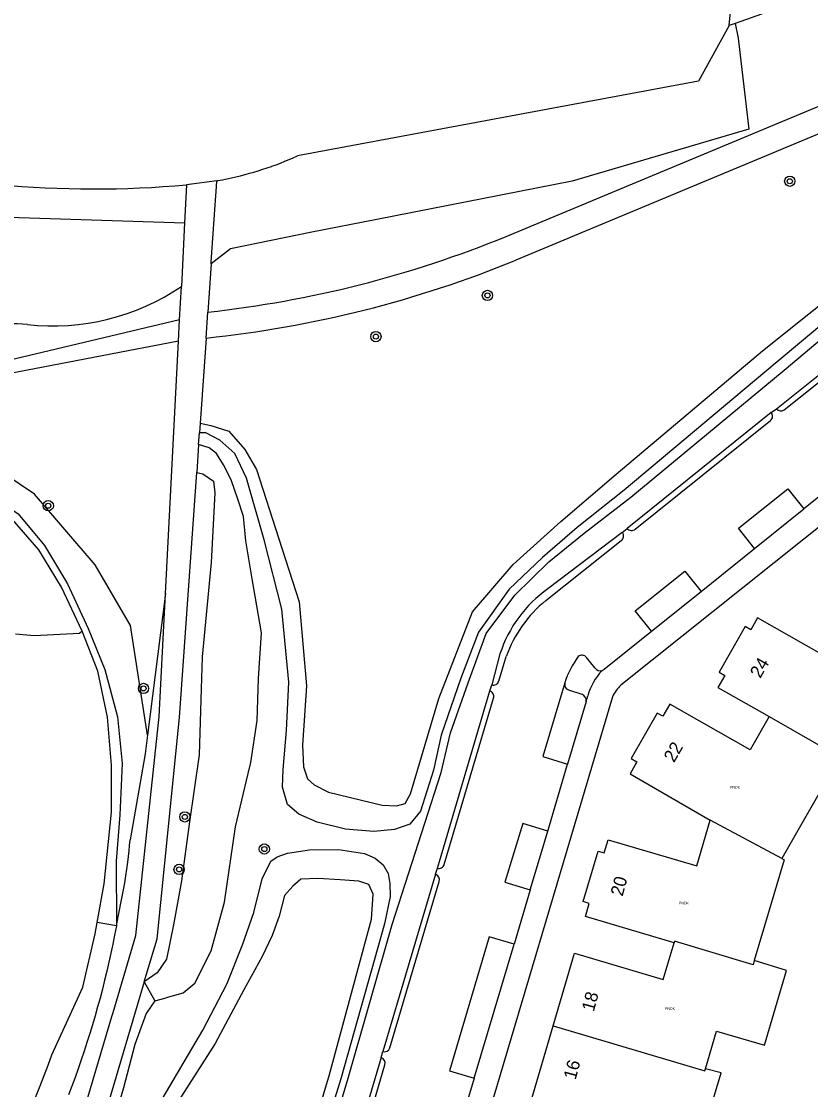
# Model space of a CAD drawing. Extents: x 131000 to 133013, y 393000 to 396501.
# Drawn here: x 131784.2 to 131845.9, y 393574.7 to 393658.1 of the extents above; entities that cross this region are included whole.
import ezdxf

# ---------------------------------------------------------------- set-up
doc = ezdxf.new("R2010")
doc.units = 0
for name, color, linetype in [('gg-anno-huisnummerreeks BGT', 7, 'Continuous'), ('gg-knt-BGT kruinlijn', 7, 'Continuous'), ('gg-knt-onverhard', 7, 'Continuous'), ('gg-knt-verharding', 7, 'Continuous'), ('gg-kntw-bovenkant insteek waterloop', 7, 'Continuous'), ('gt-grn-groengrens', 7, 'Continuous'), ('gt-grn-vlakafsluiter', 7, 'Continuous'), ('gt-grn-weggrens', 7, 'Continuous'), ('gt-symb-boom', 7, 'Continuous'), ('gx-grn-maaiveld', 7, 'Continuous'), ('kenmerkpunt-x pandkandidaat', 7, 'Continuous')]:
    doc.layers.add(name, color=color, linetype=linetype)

# ---------------------------------------------------------------- blocks, each defined once
blk = doc.blocks.new('gt0-BOOM')
at = {"layer": 'gt-symb-boom'}
for radius in [0.4, 0.2]:
    blk.add_circle((0, 0), radius, dxfattribs=at)

msp = doc.modelspace()

# ---------------------------------------------------------------- linework, layer by layer
at = {"layer": 'gg-knt-BGT kruinlijn'}
for centre, radius, start, end in [((131786.692, 393652.185), 17.828, 263.57812, 304.20021), ((131782.9, 393607.496), 27.033, 86.18657, 99.87919)]:
    msp.add_arc(centre, radius, start, end, dxfattribs=at)
at = {"layer": 'gg-knt-onverhard'}
msp.add_arc((131711.634, 393604.015), 79.523, 330.61623, 340.48685, dxfattribs=at)
at = {"layer": 'gg-knt-verharding'}
for points in [[(131796.578, 393634.838), (131778.378, 393630.518), (131767.878, 393627.802), (131764.657, 393626.561)], [(131796.492, 393633.169), (131778.587, 393629.73), (131768.274, 393626.941), (131766.914, 393626.617)], [(131765.738, 393626.336), (131770.912, 393625.448), (131775.649, 393624.147), (131780.69, 393621.949), (131783.976, 393619.695), (131786.03, 393617.224), (131787.811, 393614.212), (131789.437, 393610.74), (131790.744, 393607.55), (131791.719, 393603.84), (131792.083, 393600.198), (131791.902, 393596.2), (131791.625, 393592.581), (131791.64, 393587.519)], [(131788.965, 393610.52), (131787.356, 393613.953), (131785.592, 393616.875), (131783.522, 393619.248), (131780.378, 393621.325), (131775.291, 393623.346), (131770.717, 393624.619), (131765.625, 393625.212), (131761.087, 393624.434), (131755.985, 393623.751), (131750.527, 393623.493), (131748.086, 393623.402)], [(131790.136, 393587.781), (131790.682, 393590.797), (131791.247, 393596.389), (131791.254, 393600.062), (131790.954, 393603.813), (131790.194, 393607.399), (131788.965, 393610.52)], [(131786.59, 393577.452), (131789.014, 393582.748), (131789.979, 393586.917), (131790.136, 393587.781)]]:
    msp.add_lwpolyline(points, dxfattribs=at)
at = {"layer": 'gg-kntw-bovenkant insteek waterloop'}
for p, q in [((131797.124, 393645.366), (131796.97, 393642.392)), ((131796.97, 393642.392), (131796.713, 393637.44))]:
    msp.add_line(p, q, dxfattribs=at)
msp.add_arc((131789.854, 393728.833), 83.783, 264.90497, 274.97818, dxfattribs=at)
at = {"layer": 'gt-grn-groengrens'}
msp.add_line((131788.965, 393610.52), (131788.757, 393610.358), dxfattribs=at)
for points in [[(131746.11, 393634.301), (131749.983, 393634.529), (131758.9, 393636.69), (131766.465, 393639.663), (131773.761, 393641.824), (131781.597, 393642.905), (131796.97, 393642.392)], [(131794.066, 393602.399), (131792.747, 393610.972), (131789.985, 393615.707), (131785.25, 393621.231), (131780.515, 393624.388), (131772.624, 393626.756), (131766.914, 393626.617)], [(131788.757, 393610.358), (131785.227, 393610.166), (131783.768, 393610.299)]]:
    msp.add_lwpolyline(points, dxfattribs=at)
at = {"layer": 'gt-grn-vlakafsluiter'}
msp.add_lwpolyline([(131794.066, 393602.399), (131793.884, 393600.962), (131792.716, 393594.241)], dxfattribs=at)
at = {"layer": 'gt-grn-weggrens'}
msp.add_line((131791.64, 393587.519), (131790.136, 393587.781), dxfattribs=at)
at = {"layer": 'gx-grn-maaiveld'}
for p, q in [((131839.957, 393657.96), (131839.497, 393657.796)), ((131822.071, 393641.339), (131849.749, 393652.877)), ((131850.557, 393651.047), (131822.835, 393639.491)), ((131799.493, 393645.684), (131797.124, 393645.366)), ((131799.043, 393639.213), (131798.78, 393635.436)), ((131796.578, 393634.838), (131796.713, 393637.44)), ((131843.175, 393627.888), (131854.464, 393636.909)), ((131843.795, 393627.806), (131854.388, 393636.274)), ((131796.492, 393633.169), (131796.578, 393634.838)), ((131798.639, 393633.41), (131798.78, 393635.436)), ((131795.471, 393613.469), (131796.492, 393633.169)), ((131798.639, 393633.41), (131798.177, 393626.762)), ((131842.765, 393627.592), (131831.525, 393618.551)), ((131842.765, 393627.592), (131843.175, 393627.888)), ((131798.177, 393626.762), (131798.125, 393626.013)), ((131832.159, 393618.488), (131842.712, 393626.966)), ((131798.061, 393625.104), (131798.125, 393626.013)), ((131798.061, 393625.104), (131797.91, 393622.923)), ((131848.658, 393622.749), (131845.331, 393620.079)), ((131841.477, 393616.986), (131845.331, 393620.079)), ((131831.144, 393618.242), (131825.338, 393613.844)), ((131831.144, 393618.242), (131831.525, 393618.551)), ((131825.174, 393612.916), (131831.055, 393617.607)), ((131837.294, 393613.629), (131841.477, 393616.986)), ((131795.471, 393613.469), (131794.066, 393602.399)), ((131833.425, 393610.523), (131837.294, 393613.629)), ((131829.724, 393607.553), (131833.425, 393610.523)), ((131821.593, 393608.751), (131820.944, 393606.328)), ((131821.495, 393606.637), (131822.077, 393608.553)), ((131829.02, 393607.632), (131828.341, 393608.486)), ((131820.801, 393605.86), (131820.944, 393606.328)), ((131826.937, 393605.953), (131827.976, 393605.607)), ((131817.242, 393592.321), (131821.084, 393605.304)), ((131828.327, 393605.03), (131826.877, 393600.152)), ((131828.327, 393605.03), (131828.458, 393605.481)), ((131842.606, 393603.867), (131848.117, 393600.695)), ((131848.117, 393600.695), (131843.609, 393592.791)), ((131825.322, 393594.921), (131826.877, 393600.152)), ((131843.609, 393592.791), (131838.013, 393595.78)), ((131823.957, 393590.331), (131825.322, 393594.921)), ((131816.559, 393591.551), (131812.438, 393577.719)), ((131816.559, 393591.551), (131816.708, 393592.025)), ((131813, 393578.007), (131816.844, 393590.99)), ((131823.957, 393590.331), (131822.699, 393586.1)), ((131819.586, 393575.629), (131822.699, 393586.1)), ((131793.814, 393583.151), (131794.643, 393581.68)), ((131812.321, 393577.255), (131812.438, 393577.719)), ((131812.321, 393577.255), (131808.161, 393563.412)), ((131808.737, 393563.703), (131812.612, 393576.684))]:
    msp.add_line(p, q, dxfattribs=at)
for points in [[(131839.497, 393657.796), (131840.43, 393667.378), (131828.861, 393662.74), (131829.602, 393670.697), (131836.494, 393739.663), (131847.508, 393742.096)], [(131851.987, 393662.247), (131851.283, 393661.996), (131839.957, 393657.96)], [(131839.957, 393657.96), (131840.187, 393656.818), (131841.034, 393649.727), (131827.223, 393645.652), (131811.971, 393642.673), (131806.903, 393641.684), (131800.553, 393640.361), (131799.043, 393639.213)], [(131839.497, 393657.796), (131837.098, 393653.461), (131805.787, 393647.63)], [(131798.018, 393534.58), (131798.348, 393534.766), (131798.501, 393535.531), (131798.633, 393536.858), (131799.941, 393541.824), (131802.105, 393550.443), (131805.889, 393562.825), (131809.673, 393575.457), (131813.175, 393587.644), (131816.997, 393599.497), (131817.742, 393602.597), (131819.099, 393606.501), (131820.513, 393610.351), (131822.762, 393613.333), (131825.407, 393615.94), (131828.176, 393618.18), (131831.806, 393620.98), (131843.784, 393630.908), (131854.149, 393639.623), (131859.745, 393643.867), (131863.364, 393646.398), (131864.487, 393646.819), (131865.087, 393647.085), (131865.418, 393647.443)], [(131799.493, 393645.684), (131799.515, 393645.688), (131799.538, 393645.692), (131799.56, 393645.696), (131799.915, 393645.763), (131800.268, 393645.835), (131800.621, 393645.911), (131800.972, 393645.993), (131801.323, 393646.079), (131801.666, 393646.168), (131801.675, 393646.17), (131801.684, 393646.173), (131801.692, 393646.175), (131802.032, 393646.268), (131802.377, 393646.367), (131802.721, 393646.471), (131803.064, 393646.58), (131803.405, 393646.693), (131803.744, 393646.811), (131803.766, 393646.819), (131804.107, 393646.943), (131804.447, 393647.071), (131804.785, 393647.204), (131805.121, 393647.342), (131805.455, 393647.483), (131805.787, 393647.63)], [(131799.043, 393639.213), (131799.052, 393639.337), (131799.414, 393644.545), (131799.434, 393644.833), (131799.493, 393645.684)], [(131914.201, 393621.083), (131876.49, 393642.549), (131831.041, 393606.305)], [(131798.177, 393626.762), (131799.014, 393626.584), (131800.426, 393626.137), (131801.668, 393624.7), (131802.571, 393623.142), (131804.334, 393617.726), (131805.919, 393612.828), (131806.475, 393606.274), (131806.165, 393601.62), (131806.242, 393599.93), (131806.569, 393598.998), (131807.084, 393598.529), (131808.204, 393597.965), (131812.38, 393596.948), (131813.509, 393596.907), (131814.202, 393597.084), (131814.603, 393597.836), (131816.81, 393605.267), (131819.458, 393612.036), (131822.62, 393615.74), (131826.352, 393619.096), (131830.675, 393622.789), (131842.095, 393632.419), (131852.81, 393640.96)], [(131853.515, 393640.141), (131843.093, 393631.425), (131831.283, 393621.542), (131827.63, 393618.61), (131824.918, 393616.285), (131822.314, 393613.809), (131819.921, 393610.458), (131818.529, 393606.866), (131817.009, 393602.399), (131816.403, 393599.689), (131815.39, 393596.481), (131814.543, 393595.454), (131813.355, 393595.055), (131811.744, 393594.88), (131809.53, 393595.085), (131807.323, 393595.623), (131805.885, 393596.245), (131804.997, 393596.996), (131804.619, 393598.364), (131804.668, 393599.726), (131804.919, 393602.78), (131805.097, 393606.556), (131804.55, 393612.259), (131803.191, 393617.671), (131801.791, 393622.463), (131800.88, 393624.404), (131799.724, 393625.427), (131798.626, 393626.01), (131798.125, 393626.013)], [(131794.643, 393581.68), (131795.513, 393581.913), (131795.554, 393581.934), (131796.849, 393582.3), (131797.758, 393583.059), (131799.029, 393585.583), (131800.082, 393589.375), (131800.94, 393595.246), (131801.934, 393599.426), (131802.134, 393600.268), (131802.639, 393603.554), (131802.746, 393606.834), (131802.974, 393610.396), (131802.235, 393614.62), (131801.744, 393617.573), (131801.559, 393619.482), (131801.135, 393620.822), (131800.592, 393622.345), (131800.004, 393623.518), (131799.466, 393624.39), (131798.881, 393624.85), (131798.061, 393625.104)], [(131793.814, 393583.151), (131794.811, 393586.51), (131796.579, 393603.79), (131797.91, 393622.923)], [(131797.91, 393622.923), (131798.391, 393622.801), (131799.232, 393622.241), (131799.339, 393621.318), (131799.036, 393615.881), (131798.341, 393608.538), (131798.262, 393606.022), (131798.094, 393600.866), (131797.311, 393595.473), (131796.722, 393591.043), (131796.095, 393587.613), (131795.555, 393584.924), (131794.814, 393583.864), (131793.814, 393583.151)], [(131841.477, 393616.986), (131840.214, 393618.564), (131844.073, 393621.651), (131845.331, 393620.079)], [(131833.425, 393610.523), (131832.153, 393612.112), (131836.026, 393615.213), (131837.294, 393613.629)], [(131780.191, 393555.344), (131781.2, 393557.543), (131789.001, 393572.723), (131791.282, 393580.452), (131791.376, 393580.771), (131793.151, 393586.786), (131794.973, 393603.862), (131795.471, 393613.469)], [(131849.458, 393610.621), (131847.973, 393608.014), (131841.708, 393611.583), (131841.174, 393610.645), (131840.739, 393610.892), (131838.71, 393607.33), (131839.144, 393607.082), (131838.609, 393606.144), (131842.606, 393603.867)], [(131826.653, 393606.487), (131826.425, 393605.719), (131824.93, 393600.736), (131826.877, 393600.152)], [(131816.708, 393592.025), (131816.862, 393592.546), (131820.801, 393605.86)], [(131830.381, 393605.406), (131820.552, 393572.299), (131802.733, 393512.525)], [(131842.606, 393603.867), (131841.121, 393601.26), (131834.848, 393604.834), (131834.308, 393603.887), (131833.874, 393604.135), (131831.849, 393600.581), (131832.284, 393600.334), (131831.751, 393599.4), (131838.013, 393595.78)], [(131835.187, 393586.208), (131828.263, 393588.252), (131828.567, 393589.283), (131828.088, 393589.425), (131829.248, 393593.357), (131829.728, 393593.215), (131830.032, 393594.246), (131836.957, 393592.202), (131838.013, 393595.78)], [(131825.322, 393594.921), (131823.374, 393595.512), (131821.983, 393590.93), (131823.957, 393590.331)], [(131791.64, 393587.519), (131791.769, 393588.229), (131791.886, 393588.758), (131791.996, 393589.288), (131792.1, 393589.819), (131792.198, 393590.352), (131792.29, 393590.885), (131792.375, 393591.42), (131792.453, 393591.956), (131792.525, 393592.492), (131792.527, 393592.504), (131792.581, 393592.938), (131792.63, 393593.372), (131792.675, 393593.806), (131792.716, 393594.241)], [(131794.946, 393573.561), (131798.401, 393579.385), (131800.259, 393582.976), (131801.48, 393586.037), (131802.362, 393588.572), (131803.031, 393591.206), (131803.691, 393592.576), (131804.182, 393592.902), (131805.008, 393593.192), (131806.729, 393593.45), (131808.983, 393593.5), (131811.019, 393593.184), (131811.839, 393592.799), (131812.469, 393592.278), (131812.874, 393591.611), (131812.989, 393590.827), (131813.013, 393589.808), (131812.572, 393587.694), (131809.155, 393575.587), (131805.258, 393563.013)], [(131843.609, 393592.791), (131843.795, 393592.691), (131841.454, 393584.821)], [(131804.524, 393563.363), (131808.281, 393575.923), (131811.572, 393588.05), (131811.698, 393590.012), (131811.347, 393590.757), (131810.573, 393591.008), (131809.115, 393591.116), (131807.372, 393591.235), (131806.037, 393591.179), (131805.416, 393590.615), (131804.767, 393589.907), (131804.338, 393588.289), (131803.797, 393586.787), (131803.032, 393585.142), (131801.582, 393582.544), (131799.362, 393578.349), (131796.48, 393573.882)], [(131791.64, 393587.519), (131791.503, 393586.811), (131791.36, 393586.103), (131791.21, 393585.397), (131791.054, 393584.693), (131790.89, 393583.99), (131790.72, 393583.289), (131790.543, 393582.589), (131790.36, 393581.891), (131790.17, 393581.195), (131789.973, 393580.501), (131789.769, 393579.809), (131789.559, 393579.119), (131789.342, 393578.43), (131789.118, 393577.744), (131788.888, 393577.06), (131788.652, 393576.379), (131788.408, 393575.699), (131788.159, 393575.022), (131787.902, 393574.348)], [(131822.699, 393586.1), (131820.75, 393586.677), (131817.65, 393576.202), (131819.586, 393575.629)], [(131825.745, 393579.722), (131827.416, 393585.384), (131834.341, 393583.34), (131835.187, 393586.208)], [(131841.454, 393584.821), (131841.356, 393584.492), (131835.224, 393586.331), (131835.187, 393586.208)], [(131837.637, 393576.358), (131838.495, 393579.317), (131842.249, 393578.217), (131843.976, 393584.041), (131841.454, 393584.821)], [(131793.814, 393583.151), (131790.87, 393573.226), (131790.197, 393571.898), (131786.977, 393565.55)], [(131794.643, 393581.68), (131793.968, 393580.68), (131793.078, 393578.27), (131792.187, 393574.89), (131791.375, 393572.139), (131790.065, 393570.043), (131788.702, 393566.69), (131788.205, 393565.642)], [(131830.125, 393569.058), (131830.941, 393571.822), (131824.016, 393573.866), (131825.745, 393579.722)], [(131825.745, 393579.722), (131837.598, 393576.223), (131837.637, 393576.358)], [(131819.586, 393575.629), (131818.783, 393572.927), (131817.709, 393569.316)], [(131836.239, 393567.253), (131838.861, 393576.048), (131837.637, 393576.358)]]:
    msp.add_lwpolyline(points, dxfattribs=at)
for centre, radius, start, end in [((131789.533, 393720.822), 85.885, 276.18096, 292.26283), ((131789.546, 393720.768), 87.83, 275.9424, 292.27268), ((131842.457, 393627.303), 0.422, 307.11193, 43.20931), ((131843.53, 393628.187), 0.464, 220.13798, 304.79381), ((131830.805, 393617.966), 0.437, 304.88223, 39.16085), ((131831.872, 393618.819), 0.438, 217.71869, 310.93171), ((131831.162, 393605.638), 10.063, 125.36464, 161.97956), ((131831.422, 393605.2), 9.928, 128.9993, 160.26394), ((131833.343, 393604.379), 7.014, 143.49497, 162.51252), ((131827.993, 393608.228), 0.433, 36.53759, 131.61325), ((131833.071, 393604.219), 4.782, 137.24968, 164.69507), ((131829.412, 393607.942), 0.5, 218.39653, 287.17405), ((131829.42, 393607.925), 0.481, 286.86185, 309.28312), ((131821.067, 393606.754), 0.443, 253.83418, 344.73311), ((131827.102, 393606.383), 0.461, 166.9692, 249.04204), ((131820.669, 393605.443), 0.438, 341.54426, 72.40727), ((131832.497, 393604.545), 2.284, 129.58614, 157.84542), ((131827.774, 393605.089), 0.556, 353.93716, 68.68872), ((131816.833, 393592.429), 0.423, 252.78761, 345.21222), ((131816.389, 393591.112), 0.471, 345.00961, 68.85348), ((131812.568, 393578.159), 0.458, 253.58451, 340.68173), ((131812.112, 393576.789), 0.511, 348.17854, 65.83117)]:
    msp.add_arc(centre, radius, start, end, dxfattribs=at)

# ---------------------------------------------------------------- block references
at = {"layer": 'gt-symb-boom'}
for p in [(131844.223, 393645.649), (131820.614, 393636.739), (131811.906, 393633.521), (131786.321, 393620.323), (131793.756, 393606.062), (131796.987, 393596.03), (131803.192, 393593.524), (131796.534, 393591.935)]:
    msp.add_blockref('gt0-BOOM', p, dxfattribs=at)

# ---------------------------------------------------------------- texts
at = {"layer": 'gg-anno-huisnummerreeks BGT'}
for s, rotation, p in [('24', 60, (131841.914, 393606.796)), ('22', 60, (131835.183, 393600.216)), ('20', 75, (131831.167, 393589.788)), ('18', 75, (131828.92, 393580.788)), ('16', 75, (131827.498, 393575.463))]:
    msp.add_text(s, height=1, rotation=rotation, dxfattribs=at).set_placement(p)
at = {"layer": 'kenmerkpunt-x pandkandidaat'}
for p in [(131839.563, 393598.245), (131835.571, 393589.209), (131834.49, 393580.967)]:
    msp.add_text('PNDK', height=0.2, dxfattribs=at).set_placement(p)

doc.saveas('drawing.dxf')
